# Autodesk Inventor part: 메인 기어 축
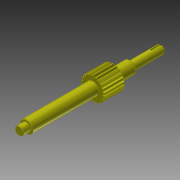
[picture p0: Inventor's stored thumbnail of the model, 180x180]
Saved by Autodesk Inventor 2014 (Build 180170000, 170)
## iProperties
Created: 2018-12
Part Number: 메인 기어 축
Material: 강철, 연강
Document SubType Name: Modeling
Designer: mduedu
Categories: <?xml version="1.0" encoding="UTF-16"?> <MemberInstance><Categories><FamilyTemplate><FamilyTemplateParameter ValueType="xs:double" Id="1" ObjectReferenceKey="da
Density: 7.86 g/cm^3
Mass: 139.66 g
Surface Area: 68.5734 cm^2
Volume: 17.7684 cm^3
Appearance: 노란색
CustomPartVersion: 1
Author: mduedu
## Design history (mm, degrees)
sketch "Sketch1"
  geometry: C1 r 11.3 at (0, 0)
  constraints: 1 centre point
  dimensions: "d0" = 22.6 diameter of C1 (= da_da)
extrude "Extrusion1" new body sketch "Sketch1" distance "d1" = 20 (= da_b); taper "d2" = 0 deg
workplane "Work Plane2"
sketch "Sketch2"
  geometry: C1 r 11.3 at (0, 0) reference; C2 r 10.5 at (0, 0)
  constraints: 1 centre point, 1 coincident
  dimensions: "d3" = 21 diameter of C2 (= da_dw)
feature "피치 지름" sketch "Sketch2" dims "d4" = 10, "d5" = 0
workplane "Work Plane8"
workplane "Work Plane9"
chamfer "모따기1" distance "d49" = 0.5; stored, may be unused: second distance "d50" = 2, angle "d51" = 45 deg
sketch "스케치3"
  geometry: C1 r 6 at (0, 0); 1 further point
  constraints: 1 centre point, 1 coincident
  dimensions: "d52" = 12 diameter of C1
extrude "돌출2" join sketch "스케치3" distance "d53" = 64; taper "d54" = 0 deg
sketch "스케치4"
  geometry: C1 r 4 at (0, 0); 1 further point
  constraints: 1 centre point, 1 coincident
  dimensions: "d55" = 8 diameter of C1
extrude "돌출3" join sketch "스케치4" distance "d56" = 7; taper "d57" = 0 deg
sketch "스케치5"
  geometry: C1 r 6 at (0, 0) reference; C2 r 6 at (0, 0) reference; 1 further point
extrude "돌출4" join sketch "스케치5" distance "d58" = 16; taper "d59" = 0 deg
sketch "스케치6"
  geometry: C1 r 4 at (0, 0); 1 further point
  constraints: 1 centre point, 1 coincident
  dimensions: "d60" = 8 diameter of C1
extrude "돌출5" join sketch "스케치6" distance "d61" = 30; taper "d62" = 0 deg
chamfer "모따기2" distance "d63" = 0.5; stored, may be unused: second distance "d64" = 2, angle "d65" = 45 deg
fillet "모깎기1" dims "d66" = 0.5
feature "스퍼 기어" dims "da_b" = 20, "da_d" = 21, "da_aw" = 31, "da_da" = 22.6, "da_df" = 19.086, "da_dw" = 21, angle "da_beta" = 0 deg, "da_lefttooth" = 0, "da_righttooth" = 0
sketch "스케치7" dims "d67" = 18
  geometry: C1 r 0.25 at (0, -9); 2 further points
  constraints: 2 vertical alignment, 1 centre point, 1 coincident, 2 other
  dimensions: "d68" = 0.5 diameter of C1
extrude "돌출6" join sketch "스케치7" distance "d69" = 0.3; taper "d70" = 0 deg
sketch "스케치8"
  geometry: L1 (4, -16)-(4, -45.5) reference; L2 (3.5, -46)-(-3.5, -46) reference; L3 (4, -46)-(2.8, -46); L4 (2.8, -46)-(2.8, -36); L5 (2.8, -36)-(4, -36); L6 (4, -36)-(4, -46); 1 further point
  constraints: 8 end point, 2 parallel, 2 point on line, 1 horizontal, 1 perpendicular
  dimensions: "d72" = 1.2 distance between parallel lines of L4 L6; "d74" = 10 distance between parallel lines of L5 L3
extrude "돌출7" cut sketch "스케치8" stored distance "d75" = 2; taper "d76" = 0 deg
fillet "모깎기2"
body "Solid1"
body "Srf1"
node "투영된 루프1"
other parameters: "d16" = 31 (= da_aw), "d17" = 0, "d34" = 1.496 (computed from da_z), "d39" = 0, "d41" = 0, "d43" = 31 (= da_aw), "d46" = 31 (= da_aw), "d47" = 0, "d48" = 0
